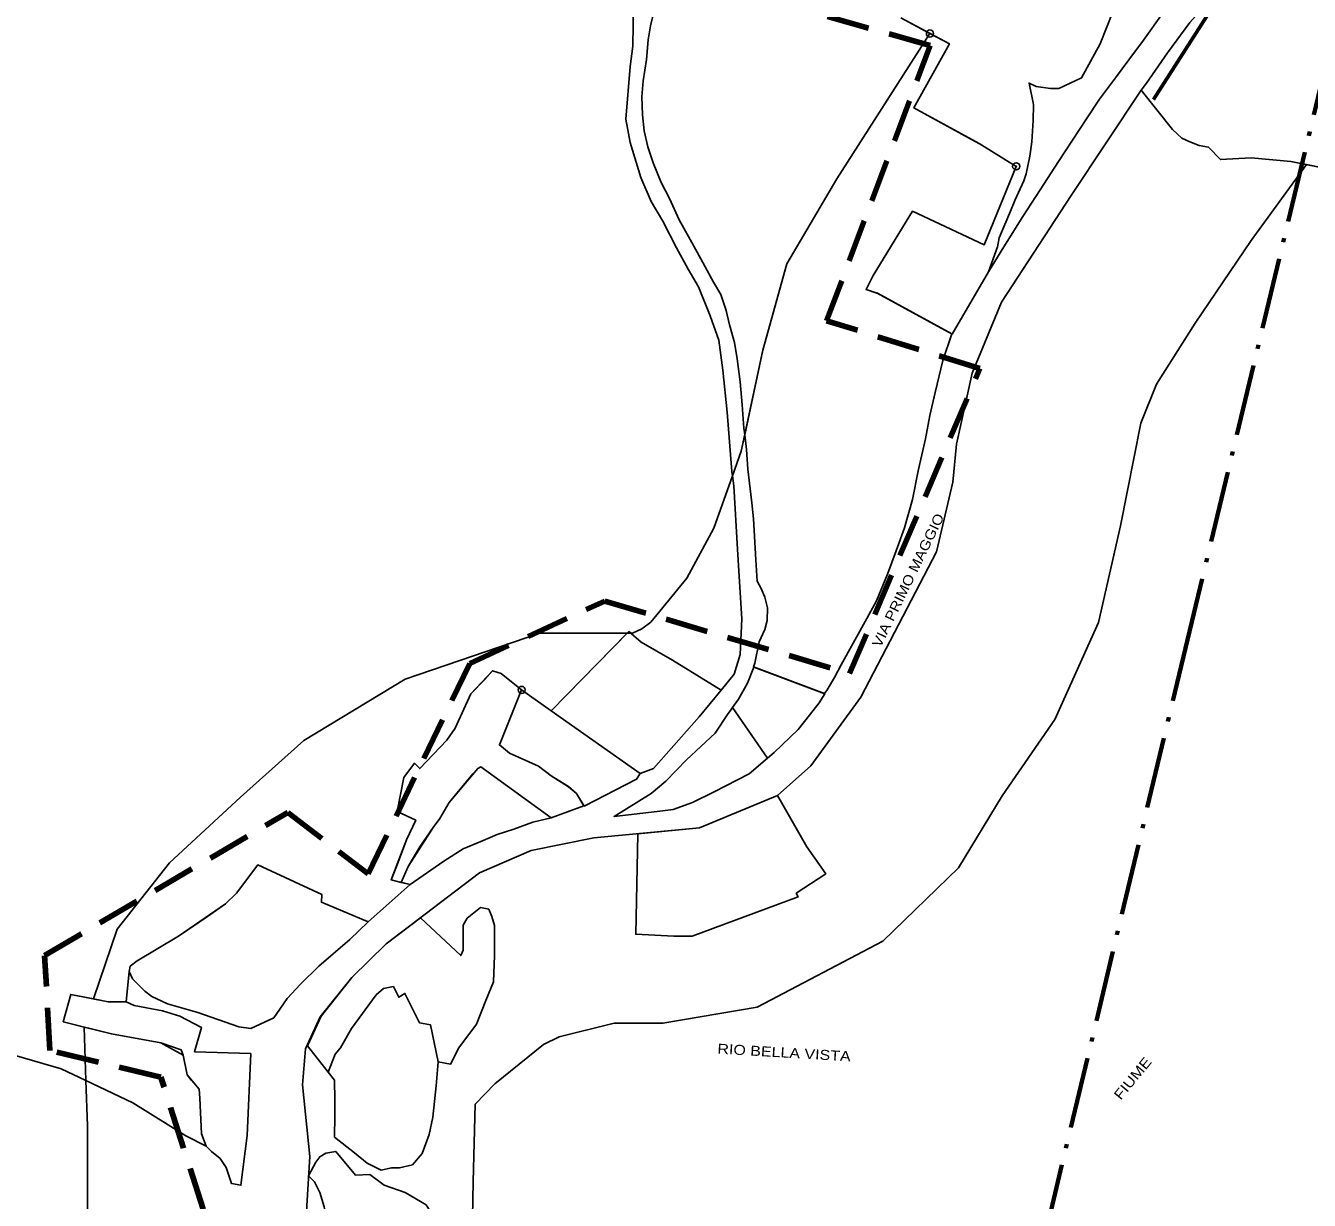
# Model space of a CAD drawing. Extents: x 654952 to 658955, y 890426 to 894481.
# Drawn here: x 657623.8 to 657984.3, y 892343.7 to 892673.6 of the extents above; entities that cross this region are included whole.
import ezdxf

# ---------------------------------------------------------------- set-up
doc = ezdxf.new("R2010")
doc.units = 0
doc.header["$LTSCALE"] = 4
doc.header["$PDMODE"] = 32
doc.header["$PDSIZE"] = 2
doc.linetypes.add('DOT_DASHED', pattern=[7.7, 5, -1.2, 0.3, -1.2])
doc.linetypes.add('MEDIUM_DASHED', pattern=[4.5, 3, -1.5])
for name, color, linetype, lineweight in [('1', 7, 'Continuous', 25), ('14', 7, 'Continuous', 25), ('29', 7, 'Continuous', 25), ('35', 7, 'Continuous', 25), ('37', 7, 'Continuous', 25), ('40', 7, 'Continuous', 60), ('43', 7, 'Continuous', 25), ('45', 7, 'Continuous', 25), ('5', 7, 'Continuous', 25), ('55', 7, 'Continuous', 25), ('7', 7, 'MEDIUM_DASHED', 100), ('9', 7, 'Continuous', 25)]:
    doc.layers.add(name, color=color, linetype=linetype, lineweight=lineweight)
doc.layers.add('58', color=7, linetype='Continuous')

msp = doc.modelspace()

# ---------------------------------------------------------------- linework, layer by layer
at = {"layer": '1'}
msp.add_lwpolyline([(657821.73, 892481.29), (657821.13, 892480.44), (657817.5, 892474.94), (657809.37, 892467.44), (657803.63, 892461.44), (657799.5, 892457.94), (657789.07, 892451.52), (657801.13, 892452.94), (657805.63, 892453.44), (657811.13, 892455.44), (657817.13, 892458.44), (657827, 892463.44), (657832.14, 892467.84), (657822.3, 892482.08)], close=True, dxfattribs=at)
for points in [[(657693.5, 892394.94), (657695.13, 892397.44), (657697.25, 892400.44), (657701, 892404.44), (657706.13, 892409.44), (657714.87, 892416.94), (657720.01, 892421.97), (657706.87, 892427.44), (657707, 892429.57), (657689, 892437.94), (657683, 892429.94)], [(657683, 892429.94), (657679.87, 892426.94), (657674.87, 892423.44), (657666.75, 892417.94), (657655.13, 892410.94), (657653.13, 892409.44), (657652.87, 892407.94), (657653.75, 892405.94), (657655.25, 892404.44), (657657.25, 892402.44), (657659.25, 892400.94), (657663.63, 892398.94), (657672.13, 892396.44), (657683.63, 892392.44), (657687, 892391.94), (657693.5, 892394.94)]]:
    msp.add_lwpolyline(points, dxfattribs=at)
at = {"layer": '14'}
msp.add_lwpolyline([(657943.13, 892676.94), (657937.75, 892669.44), (657933.63, 892663.94), (657929.87, 892658.94), (657925.37, 892652.94), (657921.75, 892647.44), (657917.87, 892641.44), (657913.87, 892635.44), (657908.75, 892627.44), (657903.87, 892619.94), (657898.5, 892611.44), (657894.25, 892604.44), (657896.75, 892611.44), (657897.25, 892613.94), (657900.44, 892621.44), (657901.63, 892624.44), (657904.13, 892629.94), (657904.81, 892631.94), (657905.87, 892636.94), (657906.37, 892640.94), (657906.75, 892646.94), (657906.87, 892651.44), (657905.63, 892657.44), (657907.63, 892656.44), (657911.63, 892655.94), (657914, 892655.94), (657920.37, 892658.94), (657925.63, 892668.44), (657929.13, 892677.44)], dxfattribs=at)
for points in [[(657763.09, 892487.04), (657756.84, 892471.6), (657759.64, 892469.3), (657767.81, 892465.6), (657771.38, 892462.92), (657776.25, 892459.94), (657778.53, 892457.94), (657780.63, 892454.44), (657795.37, 892461.94), (657796.43, 892463.56), (657771.41, 892481.13)], [(657771.38, 892451.17), (657751.63, 892465.44), (657750.75, 892464.94), (657742.75, 892455.44), (657740.13, 892450.94), (657738.25, 892448.44), (657731.25, 892437.44), (657729.25, 892432.94), (657731.75, 892432.44), (657741.25, 892438.94), (657746.63, 892442.44), (657751.63, 892444.44), (657756.25, 892446.44), (657760.87, 892447.94), (657766.25, 892449.94)], [(657708.72, 892379.67), (657710.75, 892384.8), (657712.23, 892386.56), (657715.34, 892391.96), (657722.22, 892401.42), (657724.25, 892403.18), (657727.09, 892403.72), (657728.57, 892400.74), (657730.33, 892401.83), (657734.38, 892393.58), (657737.48, 892393.04), (657739.64, 892382.64), (657739.1, 892375.9), (657738.19, 892367.09), (657737.13, 892362.23), (657735.15, 892356.91), (657732.42, 892353.72), (657728.78, 892352.81), (657726.5, 892352.81), (657723.62, 892352.2), (657719.67, 892354.18), (657716.18, 892357.06), (657710.56, 892361.47), (657710.63, 892367.44), (657710.63, 892371.94), (657710.5, 892377.44)]]:
    msp.add_lwpolyline(points, close=True, dxfattribs=at)
msp.add_point((657763.09, 892487.04), dxfattribs=at)
at = {"layer": '29'}
for points in [[(657956, 892639.44), (657953.37, 892639.94), (657950.75, 892640.94), (657948.5, 892641.94), (657945.87, 892644.44), (657937.08, 892655.43), (657938.63, 892657.44), (657944.5, 892665.94), (657950.75, 892674.44), (657956.5, 892680.94), (657965.13, 892698.44), (657970.5, 892707.19), (657975.87, 892715.94)], [(658000.87, 892634.44), (657998.75, 892631.44), (657995.75, 892631.94), (657989, 892633.44), (657979.13, 892635.44), (657968, 892636.44), (657959.38, 892635.94), (657956, 892639.44)]]:
    msp.add_lwpolyline(points, dxfattribs=at)
at = {"layer": '35'}
msp.add_line((657819.13, 892486.94), (657822.79, 892491.47), dxfattribs=at)
for points in [[(657822.32, 892547.13), (657822.16, 892548.37), (657820.79, 892565), (657819.6, 892576.8), (657818.47, 892585.29), (657816.02, 892592.12), (657812.75, 892600.19), (657809.87, 892605.19), (657806.61, 892611.14), (657802.77, 892618.64), (657799.5, 892624.21), (657796.62, 892630.93), (657793.55, 892640.73), (657792.4, 892647.27), (657793.59, 892662.1), (657794.32, 892667.8), (657794.51, 892679.74), (657793.43, 892685.48), (657791.76, 892689.35), (657788.56, 892695.31)], [(657793.82, 892502.94), (657794.27, 892502.94), (657796.85, 892504.24), (657799.35, 892506.06), (657809.46, 892518.46), (657817.09, 892532.42), (657822.32, 892547.13)], [(657822.32, 892547.13), (657817.09, 892532.42), (657809.46, 892518.46), (657799.35, 892506.06), (657796.85, 892504.24), (657794.27, 892502.94), (657793.82, 892502.94)], [(657822.79, 892491.47), (657824.52, 892496.95), (657824.9, 892507.04), (657824.23, 892518.86), (657823.75, 892526.54), (657822.66, 892544.37), (657822.32, 892547.13)], [(657642.86, 892400.26), (657649.47, 892419.86), (657664.18, 892438.49), (657684.12, 892456.94), (657701.93, 892472.84), (657730.39, 892490.02), (657768.19, 892502.94), (657792.76, 892502.94)], [(657792.76, 892502.94), (657768.19, 892502.94), (657730.39, 892490.02), (657701.93, 892472.84), (657684.12, 892456.94), (657664.18, 892438.49), (657649.47, 892419.86), (657642.86, 892400.26)], [(657734.5, 892464.94), (657742.13, 892472.94), (657744.46, 892476.32), (657748.87, 892485.94), (657754.87, 892492.44), (657757.35, 892491.64), (657763.09, 892487.04), (657771.41, 892481.13), (657792.76, 892502.94)], [(657792.76, 892502.94), (657793.25, 892503.44), (657793.82, 892502.94)], [(657793.82, 892502.94), (657796.63, 892500.44), (657805.5, 892495.44), (657819.13, 892486.94)], [(657707, 892429.57), (657706.87, 892427.44), (657720.01, 892421.97), (657731.75, 892432.44), (657726.48, 892433.68), (657730.75, 892444.94), (657733.37, 892450.44), (657728.13, 892452.94), (657730, 892462.44), (657733, 892466.44), (657734.5, 892464.94)], [(657652.87, 892407.94), (657653.13, 892409.44), (657655.13, 892410.94), (657666.75, 892417.94), (657679.87, 892426.94), (657683, 892429.94), (657689, 892437.94), (657707, 892429.57)], [(657403.85, 892420.74), (657395.9, 892411.08), (657390.46, 892401.17), (657599, 892407.44), (657607.54, 892403.45), (657610.01, 892393.05), (657610.51, 892385.78), (657615.95, 892385.78), (657633.78, 892380.66), (657640.7, 892377.37), (657640.2, 892392.38)], [(657642.86, 892400.26), (657647, 892399.44), (657652, 892399.44), (657652.87, 892407.94)], [(657640.2, 892392.38), (657634.32, 892393.87), (657636.46, 892401.53), (657642.86, 892400.26)], [(657669.13, 892378.94), (657668, 892384.44), (657667.5, 892385.94), (657661.75, 892387.94), (657647.87, 892390.44), (657640.2, 892392.38), (657640.7, 892377.37), (657653.91, 892371.08)], [(657653.91, 892371.08), (657668.77, 892361.83), (657674.5, 892358.94), (657673.13, 892362.44), (657672.75, 892372.44), (657672.5, 892374.94), (657669.13, 892378.94)]]:
    msp.add_lwpolyline(points, dxfattribs=at)
at = {"layer": '37'}
msp.add_lwpolyline([(657642.61, 892283.53), (657641.27, 892297.38), (657641.13, 892322.31), (657641.13, 892364.6), (657640.7, 892377.37), (657633.78, 892380.66), (657615.95, 892385.78), (657610.51, 892385.78), (657610.01, 892393.05), (657607.54, 892403.45), (657599, 892407.44), (657599.5, 892383.44)], dxfattribs=at)
at = {"layer": '40'}
msp.add_lwpolyline([(658114.09, 892964.13), (658054.45, 892838.86), (657981.91, 892717.36), (657940.54, 892652.83)], dxfattribs=at)
at = {"layer": '43'}
msp.add_line((657877.78, 892671.36), (657869.57, 892675.79), dxfattribs=at)
for points in [[(657983.56, 892634.54), (657998.75, 892631.44), (658000.87, 892634.44), (658011.87, 892663.07), (658023.01, 892676.46), (658032.38, 892684.45), (658040.63, 892692.44), (658047, 892703.44), (658036.31, 892709.98), (658057, 892736.94), (658058.63, 892741.44), (658069.5, 892729.94), (658073.37, 892748.94), (658079, 892762.39), (658102.13, 892822.94), (658101, 892827.94), (658107.87, 892833.47), (658114.24, 892832.91), (658119.5, 892837.28), (658146, 892832.35), (658148.87, 892834.03), (658161.16, 892853.31)], [(657800.02, 892676.55), (657799.27, 892673.55), (657798.64, 892669.55), (657798.14, 892664.05), (657797.27, 892658.05), (657796.89, 892653.55), (657797.02, 892648.55), (657797.52, 892644.05), (657798.52, 892639.55), (657800.02, 892635.05), (657802.27, 892629.55), (657804.64, 892625.05), (657807.39, 892619.05), (657810.39, 892613.55), (657813.39, 892608.05), (657817.02, 892601.55), (657819.02, 892598.05), (657820.52, 892593.55), (657821.52, 892589.55), (657822.89, 892584.55), (657823.64, 892580.05), (657824.52, 892573.55), (657825.02, 892567.05), (657825.52, 892560.55), (657825.76, 892558.67)], [(657877.78, 892671.36), (657851.62, 892630.59), (657837.6, 892606.65), (657830.8, 892582.4), (657825.76, 892558.67)], [(657825.76, 892558.67), (657830.8, 892582.4), (657837.6, 892606.65), (657851.62, 892630.59), (657877.78, 892671.36)], [(657902.02, 892634.05), (657891.65, 892640.47), (657891.5, 892640.51), (657873.25, 892650.44), (657883.25, 892668.44), (657877.78, 892671.36)], [(657937.08, 892655.43), (657917.49, 892625.83), (657897.89, 892595.91), (657889.62, 892575.97), (657885.22, 892556.03), (657884.21, 892545.38), (657879.65, 892525.77), (657858.36, 892485.03), (657844.33, 892465.76), (657835, 892457.44), (657813.09, 892448.35), (657783.36, 892445.48)], [(657953.37, 892639.94), (657950.75, 892640.94), (657948.5, 892641.94), (657945.87, 892644.44), (657937.08, 892655.43)], [(657983.57, 892634.54), (657979.13, 892635.44), (657968, 892636.44), (657959.38, 892635.94), (657956, 892639.44), (657953.37, 892639.94)], [(657864.57, 892416.48), (657885.84, 892437.05), (657898.03, 892457.31), (657912.83, 892478.72), (657925.15, 892505.95), (657931.29, 892533.08), (657936.99, 892561.98), (657941.46, 892572.89), (657952.31, 892590.01), (657968.05, 892613.19), (657983.57, 892634.54)], [(657864.57, 892416.48), (657885.84, 892437.05), (657898.03, 892457.31), (657912.83, 892478.72), (657925.15, 892505.95), (657931.29, 892533.08), (657936.99, 892561.98), (657941.46, 892572.89), (657952.31, 892590.01), (657968.05, 892613.19), (657983.56, 892634.54)], [(657848.89, 892487.05), (657851.02, 892490.55), (657852.89, 892494.05), (657860.02, 892507.05), (657862.77, 892512.05), (657865.89, 892519.55), (657868.27, 892526.05), (657870.64, 892532.55), (657872.89, 892540.55), (657874.52, 892548.55), (657876.52, 892557.55), (657877.77, 892564.05), (657879.27, 892570.55), (657881.39, 892579.55), (657883.89, 892587.05), (657863.02, 892598.48), (657862.87, 892598.48), (657859.87, 892599.44), (657861.87, 892603.44), (657872.87, 892621.44), (657893.02, 892612.05), (657902.02, 892634.05)], [(657825.76, 892558.67), (657826.27, 892554.55), (657826.64, 892549.05), (657827.14, 892545.05), (657827.77, 892539.55), (657828.27, 892535.05), (657828.89, 892523.55), (657829.27, 892517.55)], [(657829.27, 892517.55), (657830.39, 892515.55), (657831.39, 892513.05), (657832.14, 892510.05), (657832.02, 892506.55), (657831.39, 892504.05), (657829.77, 892500.55), (657828.64, 892494.55), (657828.24, 892493.56), (657848.19, 892486.01), (657848.89, 892487.05)], [(657783.36, 892445.48), (657765.79, 892441.93), (657751.26, 892435.67), (657725.06, 892415.72), (657715.43, 892406.25), (657706.48, 892395.27), (657702.43, 892386.31), (657701.58, 892376.17), (657703.61, 892356.05), (657701.75, 892325.28)], [(657750.02, 892370.71), (657755.54, 892376.45), (657769.28, 892387.51), (657773.68, 892389.67), (657789.04, 892393.44), (657802.78, 892393.44), (657829.22, 892398), (657864.57, 892416.48)], [(657750.02, 892370.71), (657755.54, 892376.45), (657769.28, 892387.51), (657773.68, 892389.67), (657789.04, 892393.44), (657802.78, 892393.44), (657829.22, 892398), (657864.57, 892416.48)], [(657780.84, 892224.82), (657777.08, 892222.16), (657773.41, 892234.07), (657764.09, 892253.86), (657753.01, 892282.56), (657749.48, 892296.7), (657748.68, 892304.16), (657749.49, 892348.88), (657750.02, 892370.71)], [(657780.84, 892224.82), (657777.08, 892222.16), (657773.41, 892234.07), (657764.09, 892253.86), (657753.01, 892282.56), (657749.48, 892296.7), (657748.68, 892304.16), (657749.49, 892348.88), (657750.02, 892370.71)]]:
    msp.add_lwpolyline(points, dxfattribs=at)
for points in [[(657891.52, 892640.55), (657891.5, 892640.51), (657891.63, 892640.44), (657891.65, 892640.47)], [(657862.89, 892598.55), (657862.87, 892598.48), (657863, 892598.44), (657863.02, 892598.48)]]:
    msp.add_lwpolyline(points, close=True, dxfattribs=at)
for p in [(657877.78, 892671.36), (657902.02, 892634.05)]:
    msp.add_point(p, dxfattribs=at)
at = {"layer": '45', "linetype": 'DOT_DASHED', "lineweight": 70}
msp.add_lwpolyline([(657888.75, 892244.36), (657949.53, 892498.78), (657993.28, 892680.38), (658112.95, 893179.41), (658123.49, 893235.71), (658127.84, 893290.79), (658125.12, 893359.25), (658122.7, 893382.9), (658114.35, 893470.93), (658113.32, 893505.97), (658113.89, 893537.78), (658115.35, 893563.44), (658117.94, 893594.58), (658121.29, 893618.7), (658125.97, 893646.13), (658131.56, 893672.78), (658136.29, 893692.48), (658143.9, 893719.95), (658153.86, 893751.08), (658170.87, 893795.19), (658185.72, 893828.64), (658194.88, 893846.97), (658209.57, 893874.93), (658233.56, 893914.96)], dxfattribs=at)
at = {"layer": '5'}
for points in [[(657791.76, 892689.35), (657793.43, 892685.48), (657794.51, 892679.74), (657794.32, 892667.8), (657793.59, 892662.1), (657792.4, 892647.27), (657793.55, 892640.73), (657796.62, 892630.93), (657799.5, 892624.21), (657802.77, 892618.64), (657806.61, 892611.14), (657809.87, 892605.19), (657812.75, 892600.19), (657816.02, 892592.12), (657818.47, 892585.29), (657819.6, 892576.8), (657820.79, 892565), (657822.16, 892548.37), (657822.32, 892547.13)], [(657825.76, 892558.67), (657825.52, 892560.55), (657825.02, 892567.05), (657824.52, 892573.55), (657823.64, 892580.05), (657822.89, 892584.55), (657821.52, 892589.55), (657820.52, 892593.55), (657819.02, 892598.05), (657817.02, 892601.55), (657813.39, 892608.05), (657810.39, 892613.55), (657807.39, 892619.05), (657804.64, 892625.05), (657802.27, 892629.55), (657800.02, 892635.05), (657798.52, 892639.55), (657797.52, 892644.05), (657797.02, 892648.55), (657796.89, 892653.55), (657797.27, 892658.05), (657798.14, 892664.05), (657798.64, 892669.55), (657799.27, 892673.55), (657800.02, 892676.55)], [(657822.32, 892547.13), (657824.78, 892554.06), (657825.76, 892558.67)]]:
    msp.add_lwpolyline(points, dxfattribs=at)
at = {"layer": '55'}
for points in [[(657869.57, 892675.79), (657877.78, 892671.36), (657851.62, 892630.59), (657837.6, 892606.65), (657830.8, 892582.4), (657824.78, 892554.06), (657822.32, 892547.13)], [(657956, 892639.44), (657953.37, 892639.94), (657950.75, 892640.94), (657948.5, 892641.94), (657945.87, 892644.44), (657937.08, 892655.43), (657938.63, 892657.44), (657944.5, 892665.94), (657950.75, 892674.44)], [(657983.57, 892634.54), (657979.13, 892635.44), (657968, 892636.44), (657959.38, 892635.94), (657956, 892639.44)], [(657750.02, 892370.71), (657755.54, 892376.45), (657769.28, 892387.51), (657773.68, 892389.67), (657789.04, 892393.44), (657802.78, 892393.44), (657829.22, 892398), (657864.57, 892416.48), (657885.84, 892437.05), (657898.03, 892457.31), (657912.83, 892478.72), (657925.15, 892505.95), (657931.29, 892533.08), (657936.99, 892561.98), (657941.46, 892572.89), (657952.31, 892590.01), (657968.05, 892613.19), (657983.57, 892634.54)], [(657822.32, 892547.13), (657822.66, 892544.37), (657823.75, 892526.54), (657824.23, 892518.86), (657824.9, 892507.04), (657824.52, 892496.95), (657822.79, 892491.47), (657819.13, 892486.94)], [(657819.13, 892486.94), (657805.5, 892495.44), (657796.63, 892500.44), (657793.82, 892502.94), (657792.76, 892502.94), (657771.41, 892481.13)], [(657771.41, 892481.13), (657763.09, 892487.04), (657757.35, 892491.64), (657754.87, 892492.44), (657748.87, 892485.94), (657744.46, 892476.32), (657742.13, 892472.94), (657734.5, 892464.94), (657733, 892466.44), (657730, 892462.44), (657728.13, 892452.94), (657733.37, 892450.44), (657730.75, 892444.94), (657726.48, 892433.68), (657731.75, 892432.44), (657720.01, 892421.97), (657706.87, 892427.44), (657707, 892429.57), (657689, 892437.94), (657683, 892429.94), (657679.87, 892426.94), (657666.75, 892417.94)], [(657666.75, 892417.94), (657655.13, 892410.94), (657653.13, 892409.44), (657652.87, 892407.94)], [(657652.87, 892407.94), (657652, 892399.44), (657647, 892399.44), (657642.86, 892400.26)], [(657642.86, 892400.26), (657636.46, 892401.53), (657634.32, 892393.87), (657640.2, 892392.38)], [(657640.2, 892392.38), (657647.87, 892390.44), (657661.75, 892387.94), (657668, 892384.44), (657669.13, 892378.94), (657672.5, 892374.94), (657672.75, 892372.44), (657673.13, 892362.44), (657674.5, 892358.94), (657668.77, 892361.83), (657653.91, 892371.08), (657640.7, 892377.37)], [(657640.7, 892377.37), (657641.13, 892364.6), (657641.13, 892322.31), (657641.27, 892297.38), (657642.61, 892283.53)], [(657813.86, 892150.82), (657811.18, 892159.16), (657799.22, 892181.84), (657777.08, 892222.16), (657773.41, 892234.07), (657764.09, 892253.86), (657753.01, 892282.56), (657749.48, 892296.7), (657748.68, 892304.16), (657749.49, 892348.88), (657750.02, 892370.71)]]:
    msp.add_lwpolyline(points, dxfattribs=at)
at = {"layer": '7'}
msp.add_lwpolyline([(657673.64, 892341.21), (657661.76, 892378.34), (657630.59, 892385.76), (657629.11, 892412.49), (657697.38, 892452.59), (657719.98, 892435.41), (657748.55, 892494.5), (657786.44, 892511.99), (657855.22, 892491.64), (657891.81, 892577.33), (657848.77, 892590.7), (657877.87, 892668.02), (657826.79, 892682.33)], dxfattribs=at)
at = {"layer": '9'}
for points in [[(657929.13, 892677.44), (657925.63, 892668.44), (657920.37, 892658.94), (657914, 892655.94), (657911.63, 892655.94), (657907.63, 892656.44), (657905.63, 892657.44), (657906.87, 892651.44), (657906.75, 892646.94), (657906.37, 892640.94), (657905.87, 892636.94), (657904.81, 892631.94), (657904.13, 892629.94), (657901.63, 892624.44), (657900.44, 892621.44), (657897.25, 892613.94), (657896.75, 892611.44), (657894.25, 892604.44), (657884, 892586.94), (657863, 892598.44), (657859.87, 892599.44), (657861.87, 892603.44), (657872.87, 892621.44), (657893.02, 892612.05), (657902.02, 892634.05), (657891.63, 892640.44), (657873.25, 892650.44), (657883.25, 892668.44), (657869.57, 892675.79)], [(657822.3, 892482.08), (657824, 892484.44), (657826.5, 892488.94), (657828.35, 892493.45), (657848.3, 892485.9)], [(657848.3, 892485.9), (657846.63, 892483.44), (657844, 892479.94), (657840.75, 892475.94), (657834, 892469.44), (657832.14, 892467.84), (657822.3, 892482.08)]]:
    msp.add_lwpolyline(points, dxfattribs=at)
for points in [[(657819.13, 892486.94), (657805.5, 892495.44), (657796.63, 892500.44), (657793.25, 892503.44), (657771.41, 892481.13), (657796.43, 892463.56), (657800.13, 892464.94), (657813, 892479.44)], [(657754.87, 892492.44), (657752.75, 892489.94), (657748.87, 892485.94), (657744.46, 892476.32), (657742.13, 892472.94), (657734.5, 892464.94), (657733, 892466.44), (657730, 892462.44), (657728.13, 892452.94), (657733.37, 892450.44), (657730.75, 892444.94), (657728.13, 892437.94), (657726.48, 892433.68), (657729.25, 892432.94), (657731.25, 892437.44), (657734.5, 892442.94), (657738.25, 892448.44), (657740.13, 892450.94), (657742.75, 892455.44), (657749.37, 892463.44), (657750.75, 892464.94), (657751.63, 892465.44), (657771.38, 892451.17), (657780.57, 892454.49), (657778.53, 892457.94), (657776.23, 892459.85), (657771.38, 892462.92), (657767.81, 892465.6), (657759.64, 892469.3), (657756.84, 892471.6), (657763.09, 892487.04), (657757.35, 892491.64)], [(657795.78, 892446.68), (657795.13, 892418.44), (657805.87, 892417.94), (657811, 892417.94), (657840.75, 892428.94), (657840.25, 892429.94), (657848.5, 892435.44), (657843.25, 892442.94), (657835, 892457.44), (657813.09, 892448.35)], [(657702.91, 892387.1), (657706.75, 892395.44), (657715.43, 892406.25), (657725.06, 892415.72), (657734.65, 892423.04), (657746, 892412.44), (657746.63, 892413.94), (657746.67, 892421.01), (657747.75, 892422.94), (657751.5, 892425.94), (657753.87, 892425.44), (657754.75, 892423.44), (657755.44, 892420.88), (657755.44, 892412.5), (657755.17, 892405.07), (657753.01, 892399.8), (657750.45, 892393.18), (657745.45, 892386.56), (657743.15, 892381.96), (657739.64, 892382.64), (657737.48, 892393.04), (657734.38, 892393.58), (657730.33, 892401.83), (657728.57, 892400.74), (657727.09, 892403.72), (657724.25, 892403.18), (657722.22, 892401.42), (657715.34, 892391.96), (657712.23, 892386.56), (657710.75, 892384.8), (657708.72, 892379.67)], [(657636.46, 892401.53), (657647, 892399.44), (657652, 892399.44), (657654.25, 892398.44), (657662.25, 892396.94), (657667.13, 892395.44), (657673.18, 892392.26), (657671.25, 892385.44), (657687, 892384.94), (657686, 892361.94), (657684.25, 892347.94), (657681.63, 892348.44), (657680.13, 892352.94), (657678.37, 892355.44), (657676, 892357.44), (657674.5, 892358.94), (657673.13, 892362.44), (657672.75, 892372.44), (657672.5, 892374.94), (657670.25, 892377.44), (657669.13, 892378.94), (657668, 892384.44), (657667.5, 892385.94), (657661.75, 892387.94), (657647.87, 892390.44), (657634.32, 892393.87)], [(657703.21, 892350.58), (657704.87, 892348.94), (657706.37, 892345.94), (657707.63, 892341.94), (657708.37, 892337.94), (657709.63, 892334.44), (657712.75, 892330.94), (657717.63, 892330.44), (657717.5, 892325.44), (657725.75, 892323.44), (657725.62, 892323.62), (657728.13, 892330.44), (657729, 892332.44), (657735.37, 892331.94), (657737.25, 892340.94), (657736.25, 892342.44), (657730.37, 892345.94), (657724.5, 892347.94), (657720.5, 892350.94), (657716.4, 892350.82), (657710.87, 892357.44), (657708.13, 892356.94), (657706.37, 892355.94), (657705.25, 892354.44)]]:
    msp.add_lwpolyline(points, close=True, dxfattribs=at)

# ---------------------------------------------------------------- texts
at = {"layer": '58'}
for s, height, rotation, width, p in [('VIA PRIMO MAGGIO', 2.797, 64.079, 1.15, (657863.93, 892498.74)), ('RIO BELLA VISTA', 2.802, 356.643, 1.2, (657818.02, 892384.93)), ('FIUME', 2.803, 50.542, 1.2, (657931.36, 892371.69))]:
    msp.add_text(s, height=height, rotation=rotation, dxfattribs=dict(at, width=width)).set_placement(p)

doc.saveas('drawing.dxf')
